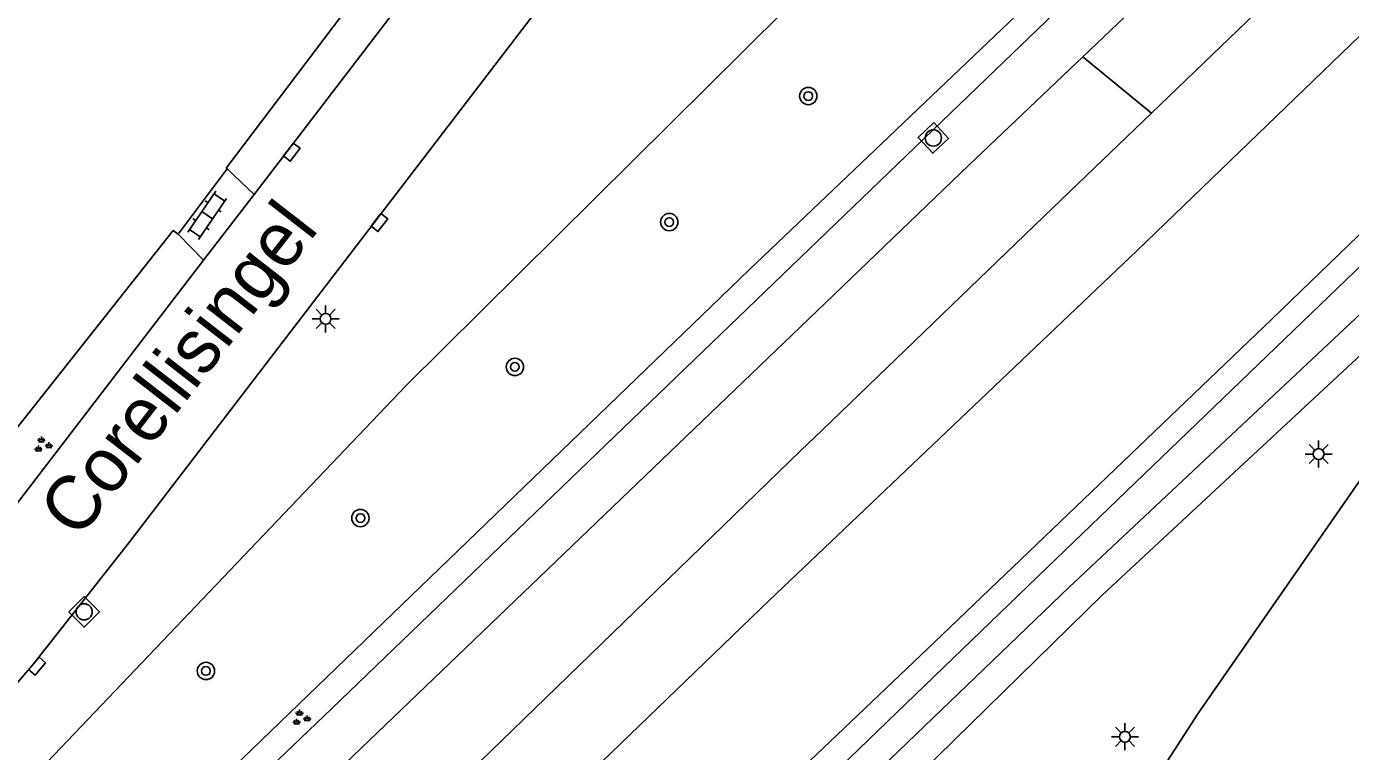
# Model space of a CAD drawing. Extents: x 137999 to 141000, y 397500 to 400501.
# Drawn here: x 138282.5 to 138343.7, y 398803.1 to 398836.6 of the extents above; entities that cross this region are included whole.
import ezdxf

# ---------------------------------------------------------------- set-up
doc = ezdxf.new("R2010")
doc.units = 0
for name, color, linetype in [('gg-afsc-erfafscheiding', 7, 'Continuous'), ('gg-anno-openbare ruimte label', 7, 'Continuous'), ('gg-knt-verharding', 7, 'Continuous'), ('gg-knt-verharding nz', 7, 'Continuous'), ('gg-kntw-bovenkant insteek waterloop', 7, 'Continuous'), ('gt-grn-groengrens', 7, 'Continuous'), ('gt-symb-boom', 7, 'Continuous'), ('gt-symb-groenvak', 7, 'Continuous'), ('gt-symb-klinker verharding', 7, 'Continuous'), ('gt-symb-kolk', 7, 'Continuous'), ('gt-symb-lichtmast', 7, 'Continuous'), ('gt-symb-rioolschacht', 7, 'Continuous'), ('gx-grn-maaiveld', 7, 'Continuous')]:
    doc.layers.add(name, color=color, linetype=linetype)

# ---------------------------------------------------------------- blocks, each defined once
blk = doc.blocks.new('gt0-GRVAK')
at = {"layer": 'gt-symb-groenvak'}
for p, q in [((-0.11, 0.189), (-0.228, 0.24)), ((-0.182, 0.153), (0.088, 0.153)), ((-0.091, 0.211), (-0.156, 0.322)), ((-0.047, 0.214), (-0.047, 0.393)), ((-0.004, 0.211), (0.061, 0.322)), ((0.015, 0.189), (0.133, 0.24)), ((0.262, -0.052), (0.197, 0.059)), ((0.305, -0.049), (0.305, 0.13)), ((0.349, -0.052), (0.414, 0.059)), ((-0.245, -0.228), (-0.363, -0.177)), ((-0.318, -0.264), (-0.047, -0.264)), ((-0.226, -0.206), (-0.291, -0.095)), ((-0.183, -0.203), (-0.183, -0.024)), ((-0.139, -0.206), (-0.074, -0.095)), ((-0.12, -0.228), (-0.002, -0.177)), ((0.243, -0.074), (0.125, -0.023)), ((0.17, -0.11), (0.441, -0.11)), ((0.368, -0.074), (0.486, -0.023))]:
    blk.add_line(p, q, dxfattribs=at)
blk = doc.blocks.new('gt0-RS')
at = {"layer": 'gt-symb-rioolschacht'}
blk.add_lwpolyline([(-0.5, -0.5), (0.5, -0.5), (0.5, 0.5), (-0.5, 0.5)], close=True, dxfattribs=at)
blk.add_circle((0, 0), 0.375, dxfattribs=at)
blk = doc.blocks.new('gt0-KL1')
at = {"layer": 'gt-symb-klinker verharding'}
for p, q in [((-1.15, 0.3), (1.15, 0.3)), ((-1, -0.3), (-1, 0.3)), ((-0.5, 0.3), (-0.5, 0.45)), ((0, -0.3), (0, 0.3)), ((0.5, 0.3), (0.5, 0.45)), ((1, -0.3), (1, 0.3)), ((-1.15, -0.3), (1.15, -0.3)), ((-0.5, -0.45), (-0.5, -0.3)), ((0.5, -0.45), (0.5, -0.3))]:
    blk.add_line(p, q, dxfattribs=at)
blk = doc.blocks.new('gt0-KOLK')
at = {"layer": 'gt-symb-kolk'}
blk.add_lwpolyline([(0, 0), (0.375, 0), (0.375, 0.4), (-0.375, 0.4), (-0.375, 0), (0, 0)], dxfattribs=at)
blk = doc.blocks.new('gt0-LMAST')
at = {"layer": 'gt-symb-lichtmast'}
for p, q in [((-0.005, 0.246), (-0.005, 0.621)), ((-0.182, 0.173), (-0.447, 0.438)), ((0.172, 0.173), (0.437, 0.438)), ((-0.255, -0.004), (-0.63, -0.004)), ((-0.182, -0.181), (-0.447, -0.446)), ((-0.005, -0.254), (-0.005, -0.629)), ((0.437, -0.446), (0.172, -0.181)), ((0.245, -0.004), (0.62, -0.004))]:
    blk.add_line(p, q, dxfattribs=at)
blk.add_circle((-0.005, -0.004), 0.25, dxfattribs=at)
blk = doc.blocks.new('gt0-BOOM')
at = {"layer": 'gt-symb-boom'}
for radius in [0.4, 0.2]:
    blk.add_circle((0, 0), radius, dxfattribs=at)

msp = doc.modelspace()

# ---------------------------------------------------------------- linework, layer by layer
at = {"layer": 'gg-afsc-erfafscheiding'}
for points in [[(138299.121, 398858.856), (138305.82, 398852.124), (138306.161, 398849.091), (138291.747, 398830.045), (138291.783, 398830.011)], [(138275.241, 398809.437), (138289.295, 398827.167), (138289.523, 398826.986)]]:
    msp.add_lwpolyline(points, dxfattribs=at)
at = {"layer": 'gg-knt-verharding'}
for p, q in [((138307.283, 398847.421), (138293.031, 398828.83)), ((138291.783, 398830.011), (138289.523, 398826.986)), ((138293.031, 398828.83), (138291.783, 398830.011)), ((138289.523, 398826.986), (138290.686, 398825.787)), ((138290.686, 398825.787), (138281.093, 398813.272))]:
    msp.add_line(p, q, dxfattribs=at)
for points in [[(138340.365, 398847.108), (138328.107, 398835.341), (138296.624, 398805.072), (138265.928, 398775.727), (138259.024, 398769.152)], [(138281.4, 398805.45), (138282.843, 398807.147), (138287.236, 398812.721), (138312.36, 398845.504)], [(138294.913, 398712.143), (138309.82, 398737.402), (138322.017, 398754.463), (138333.132, 398771.607), (138349.034, 398796.351), (138354.923, 398804.77), (138366.798, 398821.995), (138362.41, 398824.804), (138365.501, 398828.832), (138361.395, 398831.753), (138358.695, 398827.756), (138354.591, 398830.601), (138336.708, 398804.857), (138309.383, 398762.583), (138313.506, 398759.893), (138312.808, 398758.792), (138293.408, 398771.274), (138265.171, 398744.617)]]:
    msp.add_lwpolyline(points, dxfattribs=at)
at = {"layer": 'gg-knt-verharding nz'}
msp.add_line((138293.031, 398828.83), (138290.686, 398825.787), dxfattribs=at)
at = {"layer": 'gg-kntw-bovenkant insteek waterloop'}
for points in [[(138260.79, 398746.134), (138261.463, 398746.923), (138275.095, 398760.78), (138290.474, 398775.753), (138324.509, 398808.136), (138340.115, 398823.075), (138365.638, 398847.695)], [(138298.711, 398777.46), (138332.251, 398810.302), (138359.1, 398835.242)]]:
    msp.add_lwpolyline(points, dxfattribs=at)
at = {"layer": 'gt-grn-groengrens'}
for points in [[(138339.604, 398847.9), (138315.935, 398825.336), (138286.831, 398797.302), (138267.715, 398779.045), (138227.886, 398740.882), (138209.411, 398724.164), (138198.987, 398714.875), (138197.423, 398713.387), (138195.089, 398712.219), (138194.097, 398711.779)], [(138324.502, 398844.225), (138300.048, 398819.986), (138282.213, 398801.273), (138206.309, 398727.814), (138192.113, 398714.027), (138194.097, 398711.779)]]:
    msp.add_lwpolyline(points, dxfattribs=at)
at = {"layer": 'gx-grn-maaiveld'}
msp.add_line((138331.363, 398835.183), (138334.531, 398832.589), dxfattribs=at)
for points in [[(138334.531, 398832.589), (138347.741, 398845.278), (138366.674, 398863.623), (138387.38, 398883.585), (138411.492, 398906.852), (138423.765, 398918.743), (138452.891, 398946.106), (138471.751, 398963.017), (138484.511, 398974.607), (138495.454, 398984.774)], [(138499.407, 398982.656), (138489.916, 398973.847), (138478.635, 398963.661), (138469.403, 398955.249), (138460.33, 398947.221), (138453.633, 398941.068), (138444.667, 398932.821), (138432.975, 398921.772), (138417.262, 398906.589), (138399.636, 398889.594), (138385.045, 398875.638), (138367.167, 398858.322), (138349.331, 398841.156), (138333.867, 398826.239), (138316.875, 398810.072), (138304.822, 398798.46), (138292.221, 398786.299), (138279.233, 398773.798), (138267.431, 398762.44), (138257.964, 398753.347), (138247.335, 398743.355), (138238.393, 398734.962), (138228.544, 398725.848), (138219.702, 398717.858)], [(138407.514, 398907.923), (138393.606, 398894.663), (138361.787, 398864.17), (138331.363, 398835.183)], [(138305.83, 398724.637), (138322.817, 398751.754), (138332.857, 398766.915), (138346.281, 398787.384), (138364.412, 398813.993), (138388.323, 398848.076), (138388.91, 398849.825), (138388.372, 398852.686), (138383.247, 398857.02), (138380.055, 398856.094), (138370.052, 398847.316), (138357.451, 398835.727), (138330.729, 398810.671), (138298.437, 398779.654), (138270.05, 398752.316), (138258.865, 398740.843), (138257.536, 398741.868), (138292.386, 398775.602), (138330.109, 398811.962), (138350.04, 398831.129), (138358.875, 398839.458), (138374.617, 398853.291), (138378.702, 398856.526), (138386.971, 398861.131)], [(138331.363, 398835.183), (138326.089, 398830.177), (138318.671, 398823.068), (138300.208, 398805.36), (138285.722, 398791.488), (138272.634, 398778.835), (138261.358, 398768.061), (138249.15, 398756.407), (138237.381, 398745.259), (138226.138, 398734.677), (138217.259, 398726.497), (138212.232, 398721.951)], [(138334.531, 398832.589), (138329.972, 398828.211), (138319.299, 398817.929)], [(138259.875, 398760.841), (138269.874, 398770.41), (138286.331, 398786.261), (138300.897, 398800.106), (138318.319, 398816.985), (138319.299, 398817.929)]]:
    msp.add_lwpolyline(points, dxfattribs=at)

# ---------------------------------------------------------------- block references
at = {"layer": 'gt-symb-boom'}
for p in [(138318.665, 398833.377), (138312.236, 398827.547), (138305.095, 398820.856), (138297.949, 398813.869), (138290.807, 398806.799)]:
    msp.add_blockref('gt0-BOOM', p, dxfattribs=at)
at = {"layer": 'gt-symb-groenvak'}
for p in [(138283.24, 398817.239), (138295.181, 398804.618)]:
    msp.add_blockref('gt0-GRVAK', p, dxfattribs=at)
at = {"layer": 'gt-symb-klinker verharding', "rotation": 55.46787543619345}
msp.add_blockref('gt0-KL1', (138290.861, 398827.866), dxfattribs=at)
at = {"layer": 'gt-symb-kolk'}
for p, rotation in [((138294.617, 398830.905), -127.39442181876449), ((138298.669, 398827.653), -127.44608017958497), ((138282.843, 398807.147), -130.3614622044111)]:
    msp.add_blockref('gt0-KOLK', p, dxfattribs=dict(at, rotation=rotation))
at = {"layer": 'gt-symb-lichtmast'}
for p in [(138296.344, 398823.08), (138342.272, 398816.831), (138333.314, 398803.761)]:
    msp.add_blockref('gt0-LMAST', p, dxfattribs=at)
at = {"layer": 'gt-symb-rioolschacht'}
for p, rotation in [((138324.446, 398831.439), -136.93481670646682), ((138285.173, 398809.534), -44.49216304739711)]:
    msp.add_blockref('gt0-RS', p, dxfattribs=dict(at, rotation=rotation))

# ---------------------------------------------------------------- texts
at = {"layer": 'gg-anno-openbare ruimte label'}
msp.add_text('Corellisingel', height=2.5, rotation=52.2, dxfattribs=at).set_placement((138284.909, 398812.826))

doc.saveas('drawing.dxf')
